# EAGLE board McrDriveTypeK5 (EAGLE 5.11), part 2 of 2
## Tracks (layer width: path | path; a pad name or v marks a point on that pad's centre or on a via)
BUZZ  (via drill 0.4)
  Top 0.254: U$25.B 15.87,66.99 21.91,67 v28.1,73.19
  Bottom 0.254: v28.1,73.19 33.18,73.19 U1.CN5-25
ENC_A  (via drill 0.4)
  Top 0.254: v27.46,53.82 23.65,53.82 21.91,53.82 v21.27,54.45
  Bottom 0.254: v27.46,53.82 29.21,53.82 30.8,55.41 32.54,55.41 33.81,54.13 U1.CN5-9 | IC1.10 17.3,55.56 17.78,56.04 20.64,56.04 21.27,55.41 v21.27,54.45 | U1.CN5-9
ENC_AA
  Bottom 0.254: IC1.11 16.03,49.16 3.97,37.15 3.97,33.97 5.4,32.54 5.4,22.17 R9.1 6.51,20.8 8.57,18.73 8.57,18.1 10.32,16.35 CN20.P$3 10.32,9.05 CN14.4
ENC_B  (via drill 0.4)
  Top 0.254: v26.67,52.86 24.45,52.86 20.48,52.86 v19.84,52.71
  Bottom 0.254: v26.67,52.86 32.7,52.86 33.97,51.59 U1.CN5-7 | v19.84,52.71 IC1.8
FL_FREE  (via drill 0.4)
  Top 0.254: U$13.P$21 26.2,33.66 28.26,35.72 v28.73,35.72 28.73,39.85 30.64,41.75 30.64,63.02 U1.CN5-18
  Bottom 0.254: R96.1 | v28.73,35.72 R96.1
FL_PWM  (via drill 0.4)
  Top 0.254: U$13.P$23 24.9,35.7 v24.92,35.72 28.1,38.89 v28.1,40.64 | v36.51,40.64 38.42,42.55 v38.42,61.75
  Bottom 0.254: R93.2 | v24.92,35.72 R93.2 | v38.42,61.75 | v38.42,61.75 U1.CN5-15 | v28.1,40.64 v36.51,40.64
FL_PWML  (via drill 0.4)
  Top 0.254: v26.83,35.72 25.55,34.44 U$13.P$22 | v26.83,35.72
  Bottom 0.254: R94.2 | v26.83,35.72 R94.2
FL_REV  (via drill 0.4)
  Top 0.254: U$13.P$19 27.5,34.17 28.1,34.77 29.69,34.77 v30.64,35.72 30.64,40.8 33.18,43.34 33.18,45.24 U1.CN5-3
  Bottom 0.254: v30.64,35.72 R95.2
FR_FREE  (via drill 0.4)
  Top 0.254: U$31.P$21 74.46,33.66 76.52,35.72 v76.99,35.72 76.99,48.1 79.22,50.32 81.44,50.32 U1.CN6-20 | U1.CN6-20
  Bottom 0.254: v76.99,35.72 R73.1 | R73.1
FR_PWM  (via drill 0.4)
  Top 0.254: U$31.P$23 73.16,35.7 v73.18,35.72 73.18,36.04 v73.18,40.64 | v41.27,40.64 v41.27,59.21
  Bottom 0.254: R70.2 | v73.18,35.72 R70.2 | v41.27,59.21 U1.CN5-13 | v41.27,40.64 v73.18,40.64
FR_PWML  (via drill 0.4)
  Top 0.254: U$31.P$22 73.81,34.44 v75.09,35.72
  Bottom 0.254: v75.09,35.72 R71.2 | R71.2
FR_REV  (via drill 0.4)
  Top 0.254: U$31.P$19 75.76,34.01 76.52,34.77 77.95,34.77 v78.9,35.72 78.9,47.78 U1.CN6-21
  Bottom 0.254: v78.9,35.72 R72.2 | R72.2 | U1.CN6-21
GND  (via drill 0.4)  (4 unrouted)
  Top 0.254: v21.59,27.46 22.22,28.26 22.3,28.18 | 28.57,28.26 U$13.P$29 | U$13.P$2 22.3,24.05 20.8,22.54 v20.8,21.59 | 31.75,28.26 31.75,27.46 | 31.75,27.46 31.75,27.41 | U$5.P$2 34.37,24.05 33.81,23.5 33.5,23.18 32.86,22.54 v32.86,21.59 | 33.65,28.26 v33.65,27.46 | 45.72,28.26 v45.72,27.46 | U$11.P$2 46.43,24.05 45.88,23.5 45.56,23.18 44.93,22.54 v44.93,21.59 | v14.45,28.26 14.45,28.1 | U$19.P$2 58.5,24.05 57.94,23.5 57.63,23.18 56.99,22.54 v56.99,21.59 | U$31.P$2 70.56,24.05 70.01,23.5 69.69,23.18 69.06,22.54 v69.06,21.59 | 57.78,28.26 v57.78,27.46 C43.1 | 69.85,28.26 v69.85,27.46 C19.1 | 31.75,27.46 C13.1 | 43.97,28.26 C41.1
  Top 0.305: U$13.P$18 28.49,31.83 U$13.P$17 | U$5.P$18 40.52,31.83 U$5.P$17 | U$11.P$17 52.62,31.83 U$11.P$18 | U$31.P$17 76.74,31.83 U$31.P$18 | U$19.P$17 64.67,31.83 U$19.P$18
  Top 0.61: U$7.P$6 14.98,27.57 14.45,28.1 14.45,30.72 | U$7.P$11 15.59,20.52 v15.4,20.48 13.65,22.23 13.65,27.46 v14.45,28.26 | 14.45,30.72 13.69,30.72 U$7.P$14 | 14.45,30.72 U$7.P$9
  Top 1.016: 28.49,31.83 28.49,28.35 28.57,28.26 | 40.52,31.83 40.52,28.26 40.64,28.26 | 52.62,31.83 52.62,28.26 52.7,28.26 | 64.67,28.26 64.67,31.83 | 76.74,31.83 76.74,28.26 76.83,28.26 | 11.66,18.17 13.97,20.48 v15.4,20.48 | 20.83,28.83 v19.53,30.16 v19.53,28.89 20.83,28.83 | 20.83,28.83 21.27,28.26
  Top 1.27: 80.17,28.26 80.17,27.25
  Top 3: v82.07,28.26 80.17,28.26 76.83,28.26 69.85,28.26 64.67,28.26 57.78,28.26 52.7,28.26 45.72,28.26 43.97,28.26 40.64,28.26 33.65,28.26 31.75,28.26 28.57,28.26 22.22,28.26 21.27,28.26
  Bottom 0.254: C29.1 R90.1 v21.59,27.46 | C40.1 R6.1 v33.65,27.46 | C50.1 R24.1 v45.72,27.46 | v15.4,20.48 14.13,19.21 13.18,19.21 R56.1 | R54.1 12.91,29.79 14.34,28.37 v14.45,28.26 | 49.05,37.94 R27.1 | 49.05,37.94 54.77,37.94 | 54.77,37.94 R29.1 | 54.77,37.94 61.12,37.94 | 61.12,37.94 66.83,37.94 | 66.83,37.94 73.18,37.94 | 73.18,37.94 78.9,37.94 | 78.9,37.94 R72.1 | 73.18,37.94 R70.1 | 66.83,37.94 R48.1 | 61.12,37.94 R39.1 | 24.92,37.94 30.64,37.94 | 30.64,37.94 36.99,37.94 | 36.99,37.94 42.7,37.94 | 42.7,37.94 49.05,37.94 | 24.92,37.94 R93.1 | 30.64,37.94 R95.1 | 36.99,37.94 R15.1 | 42.7,37.94 R17.1 | 84.45,37.15 82.39,37.94 78.9,37.94 | v57.78,27.46 R36.1 C55.1 | C60.1 R66.1 v69.85,27.46 | R55.1 12.75,25.35 v13.65,24.45 | 22.07,37.94 24.92,37.94 | C21.1
  Bottom 0.305: U$33.P$1 69.06,13.81 | U$21.P$1 56.99,14.13 | U$18.P$1 44.93,13.81 | 32.86,13.81 U$10.P$1 | U$4.P$1 20.8,13.81 | R70.1 | R15.1
  Bottom 0.406: 79.37,45.24 83.5,45.24 | 79.37,47.78 83.5,47.78 | 79.37,50.32 83.5,50.32 | 79.37,52.86 83.5,52.86 | 79.37,55.41 84.14,55.41 | 79.37,57.95 83.5,57.95 | 82.71,45.24 U1.CN6-26 81.44,45.24 81.44,43.02 | 3.02,48.26 3.33,48.58 | 3.02,48.26 | C58.2 77.47,23.13 77.47,20.48 | C53.2 65.4,23.13 65.4,20.48 | C48.2 53.34,23.13 53.34,20.48 | C31.2 41.27,23.13 41.27,20.48 | C25.2 29.21,23.13 29.21,20.48 | 79.37,60.48 83.5,60.48 | 79.37,63.02 83.5,63.02 | 79.06,73.19 83.82,73.19 | 79.06,70.65 83.82,70.65 | 79.06,68.11 83.82,68.11 | 79.06,65.56 83.82,65.56
  Bottom 0.61: 20.8,13.81 20.8,15.72 | 32.86,13.81 32.86,15.72 | 44.93,13.81 44.93,15.72 | 56.99,13.81 56.99,14.13 56.99,15.72 | 69.06,13.81 69.06,15.72
  Bottom 0.813: C35.1 70.17,63.08 70.17,70.49 | 70.17,70.49 | 70.17,70.49 IC9.5 | 70.17,70.49 IC9.4 | 3.02,48.26 3.33,48.58 4.92,48.58
  Bottom 1.016: C21.1 v19.53,30.16 | 77.63,13.97 77.63,19.37 | 65.56,13.97 65.56,19.37 | 53.5,13.97 53.5,19.37 | 41.43,13.97 41.43,19.37 | 29.37,13.97 29.37,19.37
  Bottom 3: 21.11,20.48 29.21,20.48 41.27,20.48 53.34,20.48 65.4,20.48 77.47,20.48 79.06,20.48 arc90 82.07,23.5 v82.07,27.15 v82.07,29.37 82.07,33.02 85.72,36.67 92.07,36.67 CN11.2
  other vias: 1.43,24.92 12.06,34.13 82.23,39.37 98.74,29.53 92.23,23.97 89.38,27.46 97,71.44 99.06,70.96 94.14,50.96 92.07,50.96 97.95,73.66 92.07,48.9 29.37,42.39 20.64,35.72 18.57,40.48 83.82,40.96 80.64,40.96 80.8,36.99 82.55,36.99 80.64,32.7 83.34,33.02 81.6,35.72 96.2,53.02 98.27,48.9 96.2,48.9 92.07,53.02 86.36,48.1 94.14,53.02 26.67,43.34 23.65,42.7 20.64,38.26 1.43,28.42 71.91,76.36 44.29,93.98 23.97,73.5 25.56,89.38 37.15,85.73 89.69,39.53 98.27,23.81 89.22,17.3 98.27,11.75 98.27,17.62 89.69,23.18 13.49,35.88 26.03,90.96 20.48,83.5 3.33,60.64 3.17,69.37 6.98,72.87 11.59,69.85 14.92,69.85 26.19,86.04 13.02,79.06 36.83,83.34 9.52,82.23 13.18,63.34 86.2,51.12 1.59,44.13 1.59,46.2 8.73,13.97 16.99,42.7 14.29,40.16 12.22,37.94 1.11,15.4 8.73,10.95 1.9,73.98 18.26,90.96 21.91,43.97 89.06,50.96 98.9,46.67 87.47,6.19 90.65,3.33 12.86,3.81 98.27,50.96 96.2,50.96 98.27,53.02 94.14,48.9 97,76.2 74.61,76.52 81.76,90.33 78.58,87.63 83.5,89.22 74.61,78.9 81.91,79.53 84.61,79.69 89.85,78.58 86.36,77.79 87.79,76.68 33.02,76.84 35.08,78.42 36.83,79.06 26.03,84.46 30.32,79.06 26.99,77.15 26.99,79.06 38.73,75.41 39.53,84.77 49.37,93.98 54.61,87.31 54.13,93.98 52.55,78.9 58.9,93.98 29.21,77.79 34.61,76.84 15.56,63.82 10.64,63.66 9.21,62.39 8.41,60.48 8.57,58.74 3.02,62.71 3.17,64.45 1.43,63.82 1.59,61.28 1.43,59.21 3.02,71.91 9.05,70.64 7.14,74.61 3.97,76.36 6.19,78.74 11.59,78.58 14.6,78.42 10.95,60.64 98.74,60.48 96.52,58.9 97.95,58.1 94.93,57.47 96.2,56.04 94.77,54.93 92.71,5.08 10.79,74.3 14.29,74.3 12.54,73.18 10.79,72.07 14.29,72.07 87.15,85.73 86.52,84.46 79.69,86.04 71.91,78.9 88.9,83.66 85.25,86.36 81.44,87 85.25,87.79 80.33,89.06 82.39,77.47 84.61,76.36 93.03,62.71 87.79,62.39 86.04,60.8 90.96,61.44 90.96,57.63 90.33,59.85 84.77,57.94 84.77,55.4 84.77,52.86 11.43,80.33 9.52,80.8 10.32,79.53 14.13,80.17 24.76,75.25 23.97,78.11 41.43,75.57 43.97,68.42 41.12,64.14 40.32,69.69 45.24,75.25 42.7,60.48 45.56,51.28 45.24,60.01 43.97,44.13 45.72,42.55 44.93,46.67 66.2,45.4 68.26,47.63 70.17,47.63 68.1,45.56 53.82,44.45 65.88,43.18 56.99,78.9 60.17,84.3 54.61,83.98 21.11,62.71 21.43,64.14 23.65,63.66 23.02,61.6 13.65,57.79
  pour Top (isolate 0.406, rank 2): -0.16,75.09 -0.16,32.54 100.17,32.54 100.17,75.09 80,95 20,95
  pour Bottom (isolate 0.406, rank 2): -0.16,75.09 -0.16,32.54 100.17,32.54 100.17,75.09 80,95 20,95
  pour Bottom (isolate 0.406): 100.17,-0.16 100.17,33.02 79.53,33.02 79.53,-0.16
  pour Bottom (isolate 0.254): -0.16,32.7 18.26,32.7 18.26,20.48 16.67,18.73 13.33,14.61 13.33,-0.16 -0.16,-0.16
  pour Top (isolate 0.254): -0.16,32.7 18.26,32.7 18.26,20 18.26,8.26 13.65,4.13 13.65,0 -0.16,-0.16
  pour Top (isolate 0.406): 100.17,33.34 79.22,33.34 79.22,-0.16 100.17,-0.16
  pour Bottom (isolate 0.406): 14.29,14.45 20.32,21.91 80.17,21.91 80.01,-0.16 14.29,-0.16 14.29,5.72 14.29,8.41
  pour Bottom (isolate 0.61): 59.21,49.37 72.87,49.37 76.68,45.56 78.58,43.5 78.58,81.44 59.21,81.44
  pour Top (isolate 0.61): 59.21,49.37 78.58,49.37 78.58,79.85 59.21,79.85
  pour Bottom (isolate 0.406, no thermals): 99.38,47.15 99.38,54.45 96.84,54.45 96.68,48.26 97.79,47.15
  pour Bottom (isolate 0.406, no thermals): 89.69,34.77 97.16,34.77 97.16,38.89 89.69,38.89
  pour Top (isolate 0.406, no thermals): 89.85,34.77 97.63,34.77 97.63,38.89 89.85,38.89
GYRO  (via drill 0.4)
  Top 0.254: v69,61.28 74.29,61.28 77.47,64.45 CN13.P$1
  Bottom 0.254: C34.2 | R63.2 v69,61.28
  Bottom 0.406: R63.2 C34.2 67.42,64.76 IC9.1
GYRO2
  Top 0.254: CN15.2 80.17,77.31 77.47,74.61 CN13.P$3
LED  (via drill 0.4)
  Top 0.254: v23.02,57.15 26.83,60.96 v26.83,66.84
  Top 0.61: LED3.K 2.54,34.93 v5.71,34.93
  Bottom 0.254: v5.71,34.93 5.71,37.31 23.02,54.61 v23.02,57.15 | v26.83,66.84 27.46,66.84 U1.CN5-20
LED_B  (via drill 0.4)
  Top 0.254: v43.34,88.43 43.34,85.89 U1.CN4-3
  Bottom 0.254: U$36.B 43.35,90.5 v43.34,88.43
LED_G
  Bottom 0.254: U$37.B 23.49,86.36 24.45,87.31 37.15,87.31 38.58,85.89 45.88,85.89 U1.CN4-6 | U1.CN4-6
LED_R  (via drill 0.4)
  Top 0.254: v40.48,89.22 40.48,88.74 U1.CN4-2
  Bottom 0.254: U$35.B 40.48,90.79 v40.48,89.22
N$1  (via drill 0.4, 0.6)
  Top 0.254: U$5.P$11 40.22,23.92 41.27,22.86 41.27,22.17 C2.2 41.43,21.8 41.43,16.04 40.48,15.08 38.58,15.08
  Top 1.016: v38.58,18.1 38.58,15.08 38.58,13.81 39.21,9.37 CN4.P$2
  Bottom 0.813: U$9.P$6 41.43,9.37 42.7,9.37 42.7,7.94 42.07,7.94 41.43,7.94 U$9.P$6 | U$9.P$6 | U$9.P$6 U$9.P$5
  Bottom 1.016: U$9.P$1 38.89,18.1 v38.58,18.1 | v38.58,18.1 37.78,18.1 v38.58,16.99 39.85,18.1 v38.58,18.1
  Bottom 1.778: CN4.P$2 40,5.88 arc90 42.07,7.94
N$2  (via drill 0.4)
  Top 0.254: U$13.P$24 24.25,34.49 23.49,35.24 v23.02,35.72
  Bottom 0.254: v23.02,35.72 23.02,36.04 R1.1
N$3
  Top 0.254: U$13.P$15 30.1,33.33 C26.1
N$4
  Bottom 0.254: R80.1 66.67,90.12 CN7.P$2
N$6  (via drill 0.4)
  Top 0.254: U$13.P$20 26.85,30.5 26.67,30.32 21.91,30.32 21.65,30.58 U$13.P$28 21.61,31.51 21.59,31.53 | 21.59,31.53 20.89,31.53 v20.64,31.28 | 21.59,31.53 21.65,31.53
  Bottom 0.254: R91.2 R92.2 C29.2 24.08,26.2 21.27,26.2 20.64,26.83 v20.64,31.28
N$7
  Top 0.254: CN13.P$2 81.44,70.65 U1.CN6-6
N$8  (via drill 0.4, 0.6)
  Top 0.254: U$5.P$4 35.67,23.76 34.92,23.02 34.92,22.23 C11.2 34.82,20.9 35.72,20 v35.72,18.1
  Top 1.016: v35.72,18.1 v35.72,16.99 35.72,15.4 35.72,13.81 36.67,9.37 CN4.P$1
  Bottom 0.813: U$10.P$8 33.18,9.37 34.45,9.37 34.45,7.94 33.81,7.94 33.18,7.94 U$10.P$8 | U$10.P$8 | U$10.P$8 U$10.P$7
  Bottom 1.016: v35.72,18.1 U$10.P$3 | v35.72,18.1 35.4,18.1 | v35.72,18.1 34.13,18.1 v35.72,16.99 36.19,18.1 v35.72,18.1
  Bottom 1.778: CN4.P$1 35.88,5.88 arc-90 33.81,7.94
N$9  (via drill 0.6)
  Top 0.254: U$5.P$10 39.57,23.78 40.48,22.86 40.48,16.67 v40.16,16.35
  Bottom 0.813: U$9.P$2 v40.16,16.35
N$11  (via drill 0.4)
  Top 0.254: U$13.P$25 23.6,33.07 v23.34,33.34
  Bottom 0.254: v23.34,33.34 23.34,32.23 24.76,30.8 28.05,30.8 R91.1
N$14  (via drill 0.4)
  Top 0.254: U$7.P$7 16.1,28.67 v15.56,29.21
  Bottom 0.254: v15.56,29.21 15.56,30.91 R57.1 R13.2
N$15
  Bottom 0.254: R13.1 17.62,33.23 TR1.B
N$16  (via drill 0.6)
  Top 0.254: U$5.P$12 40.87,24.06 41.75,23.18 42.07,22.86 42.7,22.23 v42.7,16.35
  Bottom 0.254: 42.7,16.51 v42.7,16.35
  Bottom 0.813: U$9.P$4 42.7,16.51
N$17  (via drill 0.6)
  Top 0.254: U$5.P$5 36.32,23.62 35.72,23.02 35.72,21.12 36.99,19.85 v36.99,16.35
  Bottom 0.813: U$10.P$4 v36.99,16.35
N$18  (via drill 0.6)
  Top 0.254: U$5.P$3 35.02,23.91 34.13,23.02 33.81,22.7 33.81,16.99 v34.45,16.35
  Bottom 0.813: v34.45,16.35 34.45,15.88 U$10.P$2
N$19
  Top 0.254: U$5.P$9 38.92,23.63 39.53,23.02 39.53,22.12 C2.1
N$20
  Top 0.61: LED3.A R14.1
N$21  (via drill 0.4, 0.6)
  Top 0.254: 26.51,15.08 28.42,15.08 29.37,16.04 29.37,21.43 29.47,21.54 C22.2 29.32,22.76 28.15,23.92 U$13.P$11
  Top 1.016: v26.51,18.1 26.51,15.08 26.51,13.81 27.15,9.37 CN1.P$2
  Bottom 1.016: v26.51,16.99 v26.51,18.1 25.72,18.1 v26.51,16.99 | v26.51,16.99 26.83,18.1 U$3.P$1 | v26.51,16.99 27.78,18.1 v26.51,18.1 | CN1.P$2 29.37,6.19 U$3.P$6 29.37,9.05 30.64,9.05
  Bottom 1.676: U$3.P$5 arc-90 27.94,5.88 CN1.P$2
N$22
  Top 0.254: C11.1 36.62,23.13 36.99,23.5 36.99,24.99 U$5.P$6
N$23  (via drill 0.4)
  Top 0.254: v32.54,32.86 32.7,32.7 33.97,32.7 34.37,32.31 U$5.P$27
  Bottom 0.254: R6.2 33.81,30.43 33.81,31.59 v32.54,32.86
N$24  (via drill 0.4)
  Top 0.254: U$5.P$7 U$5.P$8 37.94,25.56
  Top 0.61: 37.94,25.56 v37.94,23.34
  Bottom 0.254: v37.94,23.34 C31.1
N$25
  Top 0.254: U$5.P$16 41.52,33.15 C38.2
N$26
  Top 0.254: C22.1 27.52,22.97 26.85,23.63 U$13.P$9
N$27  (via drill 0.4, 0.6)
  Top 0.254: v23.65,18.1 23.65,20 22.75,20.9 C23.2 22.75,22.91 23.6,23.76 U$13.P$4
  Top 1.016: v23.65,18.1 v23.65,16.99 23.65,13.81 24.61,9.37 CN1.P$1
  Bottom 1.016: v23.65,16.99 v23.65,18.1 22.38,18.1 v23.65,16.99 | v23.65,16.99 v23.65,18.1 | v23.65,16.99 v23.65,18.1 | v23.65,16.99 U$4.P$3 | v23.65,16.99 24.13,18.1 v23.65,18.1 | CN1.P$1 22.38,6.19 U$4.P$7 22.38,9.05 21.11,9.05
  Bottom 1.676: U$4.P$8 arc90 23.65,5.88 CN1.P$1
N$28  (via drill 0.4)
  Top 0.254: v33.97,33.66 33.97,33.5 35.02,32.45 U$5.P$26
  Bottom 0.254: v33.97,33.66 33.97,32.86 36.51,30.32 38.36,30.32 R8.1
N$29  (via drill 0.4)
  Top 0.254: v35.08,35.72 36.32,34.49 U$5.P$24
  Bottom 0.254: R19.1 35.08,36.04 v35.08,35.72
N$30
  Bottom 0.61: IC9.7 IC9.6
N$31
  Top 0.254: U$5.P$15 42.17,33.33 C38.1
N$32  (via drill 0.4)
  Top 0.254: v32.7,31.28 32.94,31.51 U$5.P$28 33.72,30.58 33.97,30.32 38.73,30.32 38.92,30.5 U$5.P$20
  Bottom 0.254: R8.2 R7.2 | R8.2 | R8.2 C40.2 36.14,26.2 33.5,26.2 32.7,26.99 v32.7,31.28
N$33  (via drill 0.4)
  Top 0.254: v35.4,33.34 35.67,33.07 U$5.P$25
  Bottom 0.254: v35.4,33.34 35.4,32.23 36.83,30.8 40.11,30.8 R7.1
N$37
  Top 0.254: C23.1 24.55,23.13 24.92,23.5 24.92,24.99 U$13.P$6
N$39  (via drill 0.4, 0.6)
  Top 0.254: 50.64,15.08 52.55,15.08 53.5,16.04 53.5,21.86 C42.2 53.34,22.02 53.34,22.86 52.28,23.92 U$11.P$11
  Top 1.016: v50.64,18.1 50.64,15.08 50.64,13.81 51.28,9.37 CN3.P$2
  Bottom 1.016: v50.64,18.1 v50.64,16.99 | v50.64,16.99 50.96,18.1 U$12.P$1 | v50.64,18.1 49.85,18.1 v50.64,16.99 | v50.64,16.99 51.91,18.1 v50.64,18.1 | CN3.P$2 53.5,6.19 U$12.P$6 53.5,9.05 54.77,9.05
  Bottom 1.676: U$12.P$5 arc-90 52.23,5.88 CN3.P$2
N$40  (via drill 0.4, 0.6)
  Top 0.254: U$11.P$4 47.73,23.76 46.99,23.02 46.99,22.33 C44.2 46.88,20.9 47.78,20 v47.78,18.1
  Top 1.016: v47.78,18.1 v47.78,16.99 47.78,13.81 48.74,9.37 CN3.P$1
  Bottom 1.016: v47.78,16.99 v47.78,18.1 | v47.78,18.1 U$18.P$3 | v47.78,18.1 46.2,18.1 v47.78,16.99 | v47.78,16.99 48.26,18.1 v47.78,18.1 | CN3.P$1 46.51,6.19 U$18.P$7 46.51,9.05 45.24,9.05
  Bottom 1.676: U$18.P$8 arc90 47.62,5.88 CN3.P$1
N$41  (via drill 0.6)
  Top 0.254: U$11.P$10 51.63,23.78 52.55,22.86 52.55,16.67 v52.23,16.35
  Bottom 0.813: U$12.P$2 v52.23,16.35
N$42  (via drill 0.6)
  Top 0.254: U$11.P$12 52.93,24.06 54.77,22.23 v54.77,16.35
  Bottom 0.813: U$12.P$4 v54.77,16.35
N$43  (via drill 0.6)
  Top 0.254: U$11.P$5 48.38,23.62 47.78,23.02 47.78,21.12 49.05,19.85 v49.05,16.35
  Bottom 0.813: U$18.P$4 v49.05,16.35
N$44  (via drill 0.6)
  Top 0.254: U$11.P$3 47.08,23.91 46.2,23.02 45.88,22.7 45.88,16.99 v46.51,16.35
  Bottom 0.813: U$18.P$2 v46.51,16.35
N$46
  Bottom 0.254: CN20.P$4 12.22,16.19 10.64,17.78 9.68,17.78 9.05,18.42 9.05,19.37 7.62,20.8 7.62,22.7 R10.1 6.19,24.13 6.19,32.7 4.6,34.29 4.6,36.99 18.57,50.9 IC1.9
N$47
  Top 0.254: C42.1 51.59,21.96 51.59,23.02 50.98,23.63 U$11.P$9
N$48
  Top 0.254: U$11.P$6 49.03,23.32 48.74,23.02 48.74,22.28 C44.1
N$49  (via drill 0.4)
  Top 0.254: v44.61,32.86 44.77,32.7 46.04,32.7 46.43,32.31 U$11.P$27
  Bottom 0.254: R24.2 45.88,30.43 45.88,31.59 45.56,31.91 v44.61,32.86
N$50  (via drill 0.4)
  Top 0.254: U$11.P$8 U$11.P$7 50.01,25.56
  Top 0.61: 50.01,25.56 v50.01,23.34
  Bottom 0.254: v50.01,23.34 C48.1 | v50.01,23.34
N$51
  Top 0.254: U$11.P$16 53.58,33.15 C49.2
N$52  (via drill 0.4)
  Top 0.254: v46.04,33.66 46.04,33.5 47.08,32.45 U$11.P$26
  Bottom 0.254: v46.04,33.66 46.04,32.86 48.58,30.32 50.43,30.32 R26.1
N$53  (via drill 0.4)
  Top 0.254: U$11.P$24 48.38,34.49 v47.15,35.72
  Bottom 0.254: v47.15,35.72 47.15,36.2 R31.1
N$54
  Top 0.254: U$11.P$15 54.23,33.33 C49.1
N$55  (via drill 0.4)
  Top 0.254: U$11.P$20 50.98,30.5 50.8,30.32 46.04,30.32 45.78,30.58 U$11.P$28 45,31.51 v44.77,31.28
  Bottom 0.254: R25.2 R26.2 C50.2 48.21,26.2 45.56,26.2 44.77,26.99 v44.77,31.28
N$56  (via drill 0.4)
  Top 0.254: v47.47,33.34 47.73,33.07 U$11.P$25
  Bottom 0.254: v47.47,33.34 47.47,32.23 48.89,30.8 52.18,30.8 R25.1
N$57  (via drill 0.6)
  Top 0.254: U$13.P$10 27.5,23.78 28.42,22.86 28.42,16.67 v28.1,16.35
  Bottom 0.813: U$3.P$2 v28.1,16.35
N$58  (via drill 0.6)
  Top 0.254: U$13.P$12 28.8,24.06 29.69,23.18 29.84,23.02 30.64,22.23 v30.64,16.35
  Bottom 0.813: v30.64,16.35 30.64,15.88 U$3.P$4
N$61  (via drill 0.6)
  Top 0.254: U$13.P$5 24.25,23.62 23.65,23.02 23.65,21.12 24.92,19.85 | 24.92,19.85 | v24.92,16.35 24.92,19.85
  Bottom 0.813: v24.92,16.35 24.92,15.72 U$4.P$4
N$62
  Top 0.61: U$25.C 8.41,67.63 BZ1.-
N$65  (via drill 0.6)
  Top 0.254: U$13.P$3 22.95,23.91 22.07,23.02 | 22.07,23.02 21.75,22.7 21.75,20.8 21.75,16.99 v22.38,16.35 | 22.07,23.02
  Bottom 0.813: v22.38,16.35 22.38,15.88 U$4.P$2
N$66  (via drill 0.4)
  Top 0.254: v20.48,32.86 20.64,32.7 21.91,32.7 22.3,32.31 U$13.P$27
  Bottom 0.254: R90.2 21.75,30.48 21.75,31.59 v20.48,32.86
N$67  (via drill 0.4)
  Top 0.254: v21.91,33.66 21.91,33.5 22.95,32.48 U$13.P$26
  Bottom 0.254: v21.91,33.66 21.91,32.86 24.45,30.32 26.3,30.32 R92.1
N$68
  Bottom 0.254: R44.1 21.75,84.46 24.29,84.46 U$37.E
N$69
  Bottom 0.254: R45.1 21.43,86.36 22.86,87.79 40.64,87.79 42.21,89.36 U$36.E
N$70  (via drill 0.4, 0.6)
  Top 0.254: 62.71,15.08 64.61,15.08 65.56,16.04 65.56,21.86 C51.2 65.4,22.02 65.4,22.86 64.35,23.92 U$19.P$11
  Top 1.016: v62.71,18.1 62.71,15.08 62.71,13.81 63.34,9.37 CN5.P$2
  Bottom 0.813: U$20.P$6 65.56,9.37 66.83,9.37 U$20.P$5 | U$20.P$5 66.83,7.94 66.2,7.94 65.56,7.94 U$20.P$6 | U$20.P$5 U$20.P$6
  Bottom 1.016: v62.71,18.1 v62.71,16.99 | v62.71,16.99 63.02,18.1 U$20.P$1 | v62.71,18.1 61.91,18.1 v62.71,16.99 | v62.71,16.99 63.98,18.1 v62.71,18.1
  Bottom 1.778: CN5.P$2 64.13,5.88 arc90 66.2,7.94
N$71  (via drill 0.4, 0.6)
  Top 0.254: v59.85,18.1 59.85,20 58.95,20.9 C52.2 59.05,22.33 59.05,23.02 59.8,23.76 U$19.P$4
  Top 1.016: v59.85,18.1 v59.85,16.99 59.85,15.4 59.85,13.81 60.8,9.37 CN5.P$1
  Bottom 0.813: U$21.P$8 57.31,9.37 58.58,9.37 U$21.P$7 | U$21.P$7 58.58,7.94 57.94,7.94 57.31,7.94 U$21.P$8 | U$21.P$7 U$21.P$8
  Bottom 1.016: v59.85,18.1 59.53,18.1 | 59.53,18.1 v59.85,16.99 | v59.85,16.99 v59.85,18.1 | v59.85,16.99 U$21.P$3 | v59.85,18.1 58.26,18.1 v59.85,16.99 | v59.85,16.99 60.32,18.1 59.53,18.1
  Bottom 1.778: CN5.P$1 60.01,5.88 arc-90 57.94,7.94
N$72  (via drill 0.6)
  Top 0.254: U$19.P$10 63.7,23.78 64.61,22.86 64.61,16.67 v64.29,16.35
  Bottom 0.813: U$20.P$2 v64.29,16.35
N$73  (via drill 0.6)
  Top 0.254: U$19.P$12 65,24.06 66.83,22.23 v66.83,16.35
  Bottom 0.813: U$20.P$4 v66.83,16.35
N$74  (via drill 0.6)
  Top 0.254: U$19.P$5 60.45,23.62 59.85,23.02 59.85,21.12 61.12,19.85 v61.12,16.35
  Bottom 0.813: U$21.P$4 v61.12,16.35
N$75  (via drill 0.4)
  Top 0.254: U$13.P$7 25.88,25.56 U$13.P$8
  Top 0.61: v25.88,23.34 25.88,25.56
  Bottom 0.254: C25.1 v25.88,23.34
N$76  (via drill 0.6)
  Top 0.254: U$19.P$3 59.15,23.91 58.26,23.02 57.94,22.7 57.94,22.54 57.94,16.99 v58.58,16.35
  Bottom 0.813: U$21.P$2 v58.58,16.35
N$77
  Top 0.254: C51.1 63.66,21.96 63.66,23.02 63.05,23.63 U$19.P$9
N$78
  Top 0.254: C52.1 60.8,22.28 60.8,23.02 61.1,23.32 U$19.P$6
N$79  (via drill 0.4)
  Top 0.254: U$19.P$27 58.5,32.31 58.1,32.7 56.83,32.7 v56.67,32.86
  Bottom 0.254: v56.67,32.86 57.94,31.59 57.94,30.32 59.11,29.16 R36.2
N$80  (via drill 0.4)
  Top 0.254: U$19.P$7 62.07,25.56 U$19.P$8
  Top 0.61: 62.07,25.56 v62.07,23.34
  Bottom 0.254: v62.07,23.34 C53.1
N$81
  Top 0.254: U$13.P$16 29.45,33.15 C26.2
N$82
  Top 0.254: C54.2 65.65,33.15 U$19.P$16
N$83  (via drill 0.4)
  Top 0.254: v58.1,33.66 58.1,33.5 59.15,32.45 U$19.P$26
  Bottom 0.254: v58.1,33.66 58.1,32.86 60.64,30.32 62.49,30.32 R38.1
N$84  (via drill 0.4)
  Top 0.254: U$19.P$24 60.45,34.49 v59.21,35.72
  Bottom 0.254: v59.21,35.72 59.21,36.04 R50.1
N$85
  Top 0.254: C54.1 66.3,33.33 U$19.P$15
N$86  (via drill 0.4)
  Top 0.254: U$19.P$20 63.05,30.5 62.86,30.32 58.1,30.32 57.85,30.58 U$19.P$28 57.07,31.51 v56.83,31.28
  Bottom 0.254: R38.2 R37.2 | R38.2 | R38.2 C55.2 60.27,26.2 57.63,26.2 56.83,26.99 v56.83,31.28
N$87
  Bottom 0.254: R46.1 36.66,88.27 U$35.E
N$88  (via drill 0.4)
  Top 0.254: U$19.P$25 59.8,33.07 v59.53,33.34
  Bottom 0.254: v59.53,33.34 59.53,32.23 60.96,30.8 64.24,30.8 R37.1
N$93  (via drill 0.4, 0.6)
  Top 0.254: 74.77,15.08 76.68,15.08 77.63,16.04 77.63,21.86 C56.2 77.47,22.02 77.47,22.86 76.41,23.92 U$31.P$11
  Top 1.016: v74.77,18.1 74.77,15.08 74.77,13.81 75.41,9.37 CN2.P$2
  Bottom 1.016: v74.77,18.1 v74.77,16.99 | v74.77,16.99 75.09,18.1 U$32.P$1 | v74.77,18.1 73.98,18.1 v74.77,16.99 | v74.77,16.99 76.04,18.1 v74.77,18.1 | CN2.P$2 77.63,6.19 U$32.P$6 77.63,9.05 78.9,9.05
  Bottom 1.676: U$32.P$5 arc-90 76.36,5.88 CN2.P$2
N$94
  Bottom 1.016: U$16.IN 87.95,47.89 C16.2 90.03,44.4 D1.K
N$95  (via drill 0.4)
  Top 0.254: U$7.P$5 15.6,26.47 v15.56,26.51
  Bottom 0.254: v15.56,26.51 14.76,26.51 13.33,27.94 12.28,27.94 R54.2 10.48,27.99 R53.2
N$96
  Bottom 0.61: R40.2 1.75,9.21 CN14.1
N$97
  Bottom 1.016: U$14.P$6 U$14.P$3 90.75,40.88 D1.A
N$99
  Bottom 0.254: CN12.1 12.23,83.98 15.72,83.98 R44.2
N$100
  Bottom 0.254: R45.2 16.83,85.73 13.81,85.73 CN12.2
N$101
  Bottom 0.254: CN12.4 17.78,88.27 R46.2
N$102
  Top 0.305: R68.1 LED5.A
N$103  (via drill 0.4, 0.6)
  Top 0.254: v71.91,18.1 71.91,20 71.01,20.9 C57.2 71.12,22.17 71.12,23.02 71.86,23.76 U$31.P$4
  Top 1.016: v71.91,18.1 v71.91,16.99 71.91,13.81 72.87,9.37 CN2.P$1
  Bottom 1.016: v71.91,16.99 v71.91,18.1 | v71.91,18.1 U$33.P$3 | v71.91,18.1 70.33,18.1 v71.91,16.99 | v71.91,16.99 72.39,18.1 v71.91,18.1 | CN2.P$1 70.64,6.19 U$33.P$7 70.64,9.05 69.37,9.05
  Bottom 1.676: U$33.P$8 arc90 71.91,5.88 CN2.P$1
N$104  (via drill 0.6)
  Top 0.254: U$31.P$10 75.76,23.78 76.68,22.86 76.68,16.67 v76.36,16.35
  Bottom 0.813: U$32.P$2 v76.36,16.35
N$105  (via drill 0.6)
  Top 0.254: U$31.P$12 77.06,24.06 78.9,22.23 v78.9,16.35
  Bottom 0.813: U$32.P$4 v78.9,16.35
N$106  (via drill 0.6)
  Top 0.254: U$31.P$5 72.51,23.62 71.91,23.02 71.91,21.12 73.18,19.85 v73.18,16.35
  Bottom 0.813: U$33.P$4 v73.18,16.35
N$107  (via drill 0.6)
  Top 0.254: U$31.P$3 71.21,23.91 70.01,22.7 70.01,16.99 v70.64,16.35
  Bottom 0.813: U$33.P$2 v70.64,16.35
N$108
  Top 0.254: C56.1 75.72,21.96 75.72,23.02 75.11,23.63 U$31.P$9
N$109
  Top 0.254: C57.1 72.87,22.28 72.87,23.02 73.16,23.32 U$31.P$6
N$110  (via drill 0.4)
  Top 0.254: v17.3,62.55 21.11,66.36 22.54,66.36 29.05,72.87 29.05,73.82 v27.94,74.93 | v31.91,82.39 31.91,83.03 | 31.91,83.03 TR2.C | 31.91,83.03 33.28,84.4 R11.1
  Bottom 0.254: IC1.5 17.3,62.71 v17.3,62.55 | v27.94,74.93 31.91,78.9 v31.91,82.39
N$111  (via drill 0.4)
  Top 0.254: U$31.P$27 70.56,32.31 70.17,32.7 68.9,32.7 v68.74,32.86
  Bottom 0.254: v68.74,32.86 70.01,31.59 70.01,30.43 R66.2
N$112  (via drill 0.4)
  Top 0.254: U$31.P$7 74.14,25.56 U$31.P$8
  Top 0.61: v74.14,23.34 74.14,25.56
  Bottom 0.254: C58.1 v74.14,23.34
N$113  (via drill 0.4)
  Top 0.254: U$7.P$2 16.02,23.17 v15.4,22.54
  Bottom 0.254: v15.4,22.54 13.81,20.96 13.18,20.96 R56.2 R51.2 | R51.2
N$114  (via drill 0.4)
  Top 0.254: U$7.P$3 15.69,24.27 v15.56,24.13
  Bottom 0.254: v15.56,24.13 14.92,24.13 14.29,23.5 12.33,23.5 R55.2 10.79,23.55 R52.2
N$115
  Top 0.254: C59.2 77.71,33.15 U$31.P$16
N$116  (via drill 0.4)
  Top 0.254: v70.17,33.66 70.17,33.5 71.21,32.45 U$31.P$26
  Bottom 0.254: v70.17,33.66 70.17,32.86 72.71,30.32 74.56,30.32 R69.1
N$117  (via drill 0.4)
  Top 0.254: U$31.P$24 72.51,34.49 v71.28,35.72
  Bottom 0.254: v71.28,35.72 R74.1
N$118
  Top 0.254: C59.1 78.36,33.33 U$31.P$15
N$119
  Bottom 0.406: U$45.P$4 C32.1
N$120
  Bottom 0.406: 65.03,69.22 IC9.3 | R61.2 65.03,69.22 | C32.2 64.08,70.17 65.03,69.22
N$121
  Bottom 0.406: R62.1 61.49,64.77 C33.2 | R61.1 61.49,66.99 R62.1 | U$45.P$1 R62.1
N$122  (via drill 0.4)
  Top 0.254: U$31.P$20 75.11,30.5 74.93,30.32 70.17,30.32 69.91,30.58 U$31.P$28 69.13,31.51 v68.9,31.28
  Bottom 0.254: R67.2 R69.2 C60.2 | C60.2 | C60.2 72.34,26.2 69.69,26.2 68.9,26.99 v68.9,31.28
N$123
  Bottom 0.254: 65.93,63.98 C34.1
  Bottom 0.406: R63.1 65.93,63.98 | IC9.2 65.72,67.95 64.93,67.15 64.93,65.72 | 64.93,65.72 R62.2 | C34.1 65.62,64.72 64.93,65.72
N$124  (via drill 0.4)
  Top 0.254: v71.6,33.34 71.86,33.07 U$31.P$25
  Bottom 0.254: v71.6,33.34 71.6,32.23 73.02,30.8 76.31,30.8 R67.1
N$129
  Bottom 0.813: LCD1.P$2 3.6,54.51 C6.2
N$130
  Top 0.254: TR2.B 31.75,87.17 R28.1
N$131
  Top 0.254: R77.1 R28.2 31.75,92.08 CN10.2
N$133
  Bottom 0.813: LCD1.P$3 C5.2
N$134
  Bottom 0.813: LCD1.P$4 C5.1
N$135
  Top 0.254: R78.2 R79.2 34.29,92.39 CN10.3
P0_4
  Top 0.254: CN8.5 57.78,89.22 64.93,89.22 66.2,87.95 66.2,85.89 U1.CN3-5 | U1.CN3-5
P0_5
  Top 0.254: U1.CN3-4 63.5,88.58 57.47,88.58 56.2,89.85 54.61,89.85 CN8.4 | U1.CN3-4
P0_6
  Top 0.254: CN8.3 52.07,89.85 53.66,89.85 54.29,89.22 55.88,89.22 59.21,85.89 63.66,85.89 U1.CN3-3 | U1.CN3-3
P0_7  (via drill 0.4)
  Top 0.254: v60.01,87.16 | v60.01,87.16 U1.CN3-2
  Bottom 0.254: CN8.2 49.69,89.7 57.47,89.7 v60.01,87.16
RL_FREE  (via drill 0.4)
  Top 0.254: U$5.P$21 38.27,33.66 39.85,35.24 39.85,35.72 | 39.85,35.72 v39.85,57.95 | 39.85,35.72 v40.8,35.72
  Bottom 0.254: v40.8,35.72 R18.1 | v40.8,35.72 | v39.85,57.95 33.18,57.95 U1.CN5-14
RL_PWM  (via drill 0.4)
  Top 0.254: U$5.P$23 36.97,35.7 v36.99,35.72 36.99,39.53 v38.89,41.43 | v49.69,41.43 49.69,44.29 U1.CN4-7
  Bottom 0.254: R15.2 | v36.99,35.72 R15.2 | v38.89,41.43 v49.69,41.43
RL_PWML  (via drill 0.4)
  Top 0.254: v38.89,35.72 37.62,34.44 U$5.P$22
  Bottom 0.254: R16.2 | v38.89,35.72 R16.2
RL_REV  (via drill 0.4)
  Top 0.254: U$5.P$19 39.57,34.17 40.16,34.77 41.75,34.77 v42.7,35.72 v42.7,50.32
  Bottom 0.254: v42.7,35.72 R17.2 | U1.CN5-8 | U1.CN5-8 32.38,51.59 33.65,50.32 v42.7,50.32
RR_FREE  (via drill 0.4)
  Top 0.254: U$19.P$21 62.4,33.66 64.45,35.72 v64.93,35.72 64.93,40.16 78.9,54.13 U1.CN6-17 | U1.CN6-17
  Bottom 0.254: v64.93,35.72 R49.1 | R49.1
RR_PWM  (via drill 0.4)
  Top 0.254: U$19.P$23 61.1,35.7 v61.12,35.72 v61.12,41.75 | v48.42,42.39 48.42,83.34 U1.CN4-5
  Bottom 0.254: v61.12,35.72 R39.2 | v48.42,42.39 50.48,42.39 51.12,41.75 v61.12,41.75
RR_PWML  (via drill 0.4)
  Top 0.254: U$19.P$22 61.75,34.44 v63.02,35.72
  Bottom 0.254: v63.02,35.72 R47.2 | R47.2
RR_REV  (via drill 0.4)
  Top 0.254: U$19.P$19 63.7,34.01 64.45,34.77 65.88,34.77 v66.83,35.72 66.83,40.48 79.22,52.86 81.44,52.86 U1.CN6-18 | U1.CN6-18 | U1.CN6-18
  Bottom 0.254: v66.83,35.72 R48.2
RXD2  (via drill 0.4)
  Top 0.254: v24.13,50.32 20.64,50.32 18.57,52.39 v18.57,62.55
  Bottom 0.254: U1.CN5-5 33.97,49.05 32.7,50.32 v24.13,50.32 | v18.57,62.55 IC1.6 | IC1.6
SCL  (via drill 0.4)
  Top 0.254: v20.95,47.47 20.48,47.78 v12.06,47.78
  Bottom 0.254: LCD1.P$8 7.3,45.51 R81.1 7.67,46.2 10.48,46.2 10.95,46.67 v12.06,47.78 | U1.CN5-4 22.22,46.52 v20.95,47.47
SD_CD  (via drill 0.4)
  Top 0.254: v23.97,56.36 27.78,60.17 27.78,68.11 27.62,68.9 27.62,70.33 v29.21,71.92
  Bottom 0.254: R51.1 8.25,21.12 8.25,24.29 7.14,25.4 7.14,35.56 7.14,37.94 8.57,39.37 23.97,54.77 v23.97,56.36 | v29.21,71.92 U1.CN5-24 | U1.CN5-24
SD_CLK  (via drill 0.4)
  Top 0.254: v29.05,56.83 29.69,57.47 29.69,70.01 v29.21,70.49
  Bottom 0.254: R53.1 9.52,37.31 26.83,54.61 27.62,55.41 v29.05,56.83 | v29.21,70.49 29.37,70.65 33.18,70.65 U1.CN5-23
SD_CMD  (via drill 0.4)
  Top 0.254: v25.56,56.2 28.57,59.21 v28.57,69.06
  Bottom 0.254: R52.1 8.31,25.35 7.62,26.04 7.62,37.62 9.05,39.05 25.24,55.25 v25.56,56.2 | v28.57,69.06 28.89,69.38 U1.CN5-22 | U1.CN5-22
SD_DAT0  (via drill 0.4)
  Top 0.254: v24.61,60.01 25.88,61.28 v25.88,68.11
  Bottom 0.254: v25.88,68.11 33.18,68.11 U1.CN5-21 | IC1.12 14.76,55.56 15.72,56.52 21.11,56.52 v24.61,60.01
SD_DAT0B  (via drill 0.4)
  Top 0.254: v16.67,39.21 v12.38,46.83
  Bottom 0.254: R12.1 10.79,53.02 12.7,53.02 13.49,53.82 | 13.49,53.82 IC1.13 | TR1.C v16.67,39.21 | v12.38,46.83 13.49,47.94 13.49,53.82
SDA  (via drill 0.4)
  Top 0.254: v22.54,49.05 21.75,48.74 v12.7,48.74
  Bottom 0.254: LCD1.P$7 5.15,47.1 R75.1 9.84,47.47 11.11,48.74 v12.7,48.74 | v22.54,49.05 U1.CN5-6 | U1.CN5-6
SENS_ANL
  Top 0.254: CN6.6 86.84,70.96 U1.CN6-8
SENS_ANR
  Top 0.254: U1.CN6-9 80.64,64.3 81.91,65.56 83.98,65.56 88.11,69.69 90.96,69.69 91.6,70.33 91.6,71.6 92.87,72.87 CN6.7 | U1.CN6-9 | CN6.7
SENS_CENTER
  Top 0.254: CN6.5 | CN6.5 92.87,70.33 91.6,69.06 91.6,67.63 91.12,67.15 86.84,67.15 83.98,64.3 U1.CN6-10
SENS_GATE  (via drill 0.4)
  Top 0.254: v88.58,68.42 CN6.4 | v88.58,65.09 83.98,60.48 81.44,60.48 U1.CN6-11
  Bottom 0.254: v88.58,65.09 v88.58,68.42
SENS_L1
  Top 0.254: CN6.2 86.84,65.88 83.98,63.02 79.53,63.02 78.9,63.66 78.9,64.93 79.53,65.56 80.8,65.56 81.44,66.2 81.44,68.11 U1.CN6-5
SENS_L2
  Top 0.254: CN6.3 94.14,69.69 94.14,73.98 93.34,74.77 92.39,74.77 91.6,73.98 91.6,72.87 90.96,72.23 83.03,72.23 U1.CN6-4
SENS_R1
  Top 0.254: U1.CN6-2 83.03,74.77 91.6,74.77 CN6.9
SENS_R2
  Top 0.254: U1.CN6-3 81.44,73.19 89.53,73.19 CN6.8
SV_FREE  (via drill 0.4)
  Top 0.254: U$11.P$21 50.33,33.66 52.39,35.72 v52.86,35.72
  Bottom 0.254: v52.86,35.72 R30.1 | R30.1
SV_PWM  (via drill 0.4)
  Top 0.254: v49.05,35.72 49.03,35.7 U$11.P$23 | v49.05,35.72 | v49.05,35.72 49.05,37.31 47.15,39.21 47.15,82.55 45.88,83.82 45.88,85.89 U1.CN4-4 | U1.CN4-4
  Bottom 0.254: v49.05,35.72 R27.2
SV_PWML  (via drill 0.4)
  Top 0.254: U$11.P$22 49.68,34.44 v50.96,35.72
  Bottom 0.254: v50.96,35.72 R76.1
SV_REV  (via drill 0.4)
  Top 0.254: U$11.P$19 51.63,34.01 52.39,34.77 53.82,34.77 v54.77,35.72 50.8,39.69 v50.8,52.86
  Bottom 0.254: v54.77,35.72 R29.2 | R29.2 | v50.8,52.86 41.43,52.86 37.94,52.86 33.65,52.86 32.38,54.13 U1.CN5-10
SW1
  Top 0.254: U1.CN6-25 81.44,45.24 83.5,45.24 85.25,43.5 85.25,30.64 87.31,28.58 93.03,28.58 93.34,28.26 93.34,26.67 92.55,25.88 S1.P$3
SW2
  Top 0.254: U1.CN6-24 83.18,46.52 85.72,43.97 85.72,30.96 87.63,29.05 93.34,29.05 93.82,28.58 93.82,21.12 92.55,19.85 S2.P$3 | U1.CN6-24
SW3
  Top 0.254: U1.CN6-23 81.44,47.78 83.34,47.78 86.2,44.93 86.2,31.28 87.95,29.53 93.66,29.53 94.3,28.89 94.3,15.56 92.55,13.81 S3.P$3
SW4
  Top 0.254: U1.CN6-22 83.18,49.05 86.68,45.56 86.68,31.59 88.26,30.01 93.98,30.01 94.77,29.21 94.77,10 92.55,7.78 S4.P$3 | U1.CN6-22
TXD2  (via drill 0.4)
  Top 0.254: v29.53,43.97 30.16,44.61 30.16,74.3 v29.53,74.93 | v35.08,82.55 35.08,86.36 R79.1
  Bottom 0.254: v29.53,43.97 U1.CN5-2 | v29.53,43.97 | v29.53,74.93 | v29.53,74.93 33.34,78.74 35.08,80.49 v35.08,82.55
V33  (via drill 0.4)
  Top 0.406: CN10.1 28.1,91.12 28.1,88.58 28.89,87.79 R77.2 28.1,85.78 v28.1,84.3
  Top 0.61: U$7.P$4 14.89,25.37 v14.76,25.4
  Top 0.813: 6.67,50.01 6.67,62.07 10.16,65.56 v18.7,65.56 | 6.67,50.01 6.67,45.09 5.71,44.13 LCD1.P$9 | 6.67,50.01 LCD1.P$5
  Bottom 0.254: C7.2 | 8.25,32.23 C7.2
  Bottom 0.406: U$6.OUT 25.72,71.76 26.83,72.87 26.83,75.41 28.1,76.68 v28.1,84.3
  Bottom 0.61: R57.2 17.57,25.95 16.99,25.37 14.8,25.37 v14.76,25.4 14.45,25.72 13.49,26.67 8.73,26.67 8.25,27.15 8.25,31.91 8.25,32.23 8.25,34.61 8.25,37.15 9.84,38.74 26.83,55.72 26.83,63.18 21.11,68.9 C27.1
  Bottom 0.813: C27.1 20.8,67.63 v18.7,65.56 | C6.1 C4.2 LCD1.P$5 | LCD1.P$9 5.38,44.03 R81.2 8.41,44.03 R75.2
  Bottom 1.27: C27.1 U$6.OUT
VBAT  (via drill 0.4)
  Top 0.254: U$13.P$1 21.65,24.51 21.59,24.45 21.11,23.97 19.84,22.7 v19.84,11.59 | U$5.P$1 33.72,24.35 33.65,24.29 31.91,22.54 v31.91,11.59 | U$11.P$1 45.78,24.51 45.72,24.29 43.97,22.54 v43.97,11.59 | U$19.P$1 57.85,24.35 56.04,22.54 v56.04,11.59 | U$31.P$1 69.91,24.35 68.1,22.54 v68.1,11.59 | 79.06,25.08 v79.06,25.24 | v79.85,24.29 v78.9,23.97 | 80.17,25.08 C20.2 | v79.69,23.34 | U$19.P$14 U$19.P$13 | U$11.P$14 U$11.P$13 | U$13.P$14 U$13.P$13 | 42.31,24.53 U$5.P$13 | v85.57,23.34
  Top 0.406: U$31.P$14 U$31.P$13
  Top 1.27: 85.57,24.29 v85.09,24.29 v79.85,24.29 | v85.57,25.08 v85.57,23.34 v79.69,23.34 | 78.26,25.08 79.06,25.08 80.17,25.08 v85.57,25.08 | v85.57,25.08 | v79.69,23.34 U$31.P$14 | C19.2 68.1,24.45 v67.31,23.66 | C43.2 56.04,24.45 v55.24,23.66 | C13.2 31.91,24.45 v31.11,23.66 | v31.11,23.66 30.1,24.67 U$13.P$14 30.1,25.56 31.11,25.56 | v55.24,23.66 54.23,24.67 U$11.P$14 54.23,25.56 55.24,25.56 | v67.31,23.66 66.3,24.67 U$19.P$14 66.3,25.45 C19.2 | 31.11,25.56 31.91,25.56 | v31.11,23.66 31.11,25.56 | 55.24,25.56 56.04,25.56 | v55.24,23.66 55.24,25.56 | C19.2 67.31,25.45 v67.31,23.66 | C41.2 43.97,24.45 v43.18,23.66 | v43.18,23.66 42.31,24.53 42.17,24.67 U$5.P$14 42.17,25.56 43.18,25.56 | 43.18,25.56 43.97,25.56 | v43.18,23.66 43.18,25.56
  Bottom 0.254: 19.84,25.3 C21.2 | 86.2,25.88 v85.57,25.08 | 79.69,24.93 79.69,24.45 v79.85,24.29
  Bottom 0.61: 19.84,24.93 19.84,25.3 | U$33.P$6 71.91,7.78 76.36,7.78 U$32.P$7 | U$32.P$7 76.36,9.84 71.91,9.84 U$33.P$6 | U$33.P$6 U$33.P$5 | 71.91,11.59 U$33.P$6 | U$32.P$7 76.36,11.75 | 86.2,11.59 86.25,11.59 | U$21.P$6 59.85,7.94 64.29,7.94 U$20.P$7 64.29,9.84 | 64.29,9.84 59.85,9.84 U$21.P$6 | U$21.P$6 U$21.P$5 | 59.85,11.59 U$21.P$6 | 64.29,9.84 64.29,11.59 52.23,11.59 U$12.P$7 | U$12.P$7 52.23,7.78 47.78,7.78 U$18.P$6 | U$12.P$7 52.23,9.84 47.78,9.84 U$18.P$6 | U$18.P$6 U$18.P$5 | U$18.P$6 47.78,11.59 40.16,11.59 U$9.P$7 | U$9.P$7 | U$9.P$7 40.16,7.94 35.72,7.94 U$10.P$6 | U$10.P$6 | U$9.P$7 40.16,9.84 39.69,9.84 | 36.04,9.84 35.72,9.84 | U$10.P$6 35.72,9.84 | U$10.P$6 U$10.P$5 | 35.72,9.84 35.72,11.59 28.1,11.59 U$3.P$7 | U$3.P$7 | U$3.P$7 28.1,7.78 23.65,7.78 U$4.P$6 | U$4.P$6 | U$3.P$7 28.1,9.84 23.65,9.84 | 23.65,9.84 U$4.P$6 | U$4.P$6 U$4.P$5 | 23.65,9.84 23.65,11.59 | 86.2,26.04
  Bottom 1.016: 43.5,24.93 43.18,24.77 | U$14.P$5 U$14.P$4 | U$14.P$5 U$14.P$2 | CN11.1 92.23,32.54 96.84,32.54 98.11,33.81 98.11,41.75 U$14.P$5
  Bottom 1.27: 31.11,24.93 v31.11,23.66 | 43.18,24.77 v43.18,23.66 | 55.24,24.93 v55.24,23.66 | 67.31,24.93 v67.31,23.66 | 78.58,24.93 79.69,24.93 v79.69,23.34 U$31.P$14 | U$9.P$8 39.69,9.84 36.04,9.84 | U$21.P$5 60.32,9.53 63.98,9.53
  Bottom 1.422: 21.59,11.59 v19.84,11.59 C61.1
  Bottom 1.676: 78.58,24.93 67.31,24.93 55.24,24.93 43.5,24.93 31.11,24.93 23.18,24.93 19.84,24.93
  Bottom 1.778: U$14.P$2 U$14.P$1
  Bottom 1.93: 86.25,11.59 C14.+
  Bottom 2.184: U$9.P$8 U$10.P$5 | U$21.P$5 U$20.P$8
  Bottom 2.54: U$4.P$5 U$3.P$8 | U$18.P$5 U$12.P$8 | U$33.P$5 U$32.P$8
  Bottom 3: 21.59,11.59 v31.91,11.59 v43.97,11.59 v56.04,11.59 59.85,11.59 v68.1,11.59 71.91,11.59 86.2,11.59 86.2,25.88 86.2,26.04 86.2,30.96 87.95,32.7 CN11.1
VCC  (via drill 0.4, 0.6, 1)
  Top 0.305: R68.2 98.16,62.12 v96.84,60.8
  Top 0.406: U1.CN5-1 34.45,40.8 v32.86,39.21
  Top 0.61: v3.17,42.07 R14.2 | R11.2 33.5,81.97 33.5,80.81 | 39.53,81.76 | 39.53,81.76 39.53,80.81
  Top 0.813: BZ1.+ 4.92,74.61 4.92,59.85 v3.17,58.1 v3.17,42.07 | v74.77,74.45 v74.77,64.93
  Top 1.676: U1.CN5-1 35.72,43.97 36.67,44.93 36.67,52.86 36.67,74.3 36.67,76.36 v42.07,81.76 | v42.07,81.76 v44.29,81.76 | v44.29,81.76 | v42.07,81.76 42.07,83.98 | 42.07,83.98 42.07,84.46 | 42.07,84.46 U1.CN4-1 | v44.29,81.76 42.07,83.98 | 42.07,84.46 41.91,84.46 39.53,82.08 39.53,81.76 | v43.18,82.71 43.02,82.71 v42.07,81.76 | 39.53,80.81 39.53,79.22 | 39.53,80.81 39.53,81.76 | BZ1.+ 16.67,76.68 19.37,76.68 v23.49,80.81 26.35,80.81 | 39.53,81.76 v42.07,81.76 | 26.35,80.81 arc44 26.35,80.81 | 26.35,80.81 33.5,80.81 39.53,80.81
  Bottom 0.254: R1.2 23.02,39.85 26.83,39.85 | 28.73,39.85 26.83,39.85 | 32.86,39.85 28.73,39.85 | 35.08,39.85 R19.2 | 35.08,39.85 38.89,39.85 | 38.89,39.85 40.8,39.85 | 40.8,39.85 R18.2 | 40.8,39.85 47.15,39.85 | 47.15,39.85 R31.2 | 47.15,39.85 50.96,39.85 | 50.96,39.85 52.86,39.85 | 52.86,39.85 R30.2 | 52.86,39.85 59.21,39.85 | 59.21,39.85 R50.2 | 59.21,39.85 63.02,39.85 | 63.02,39.85 64.93,39.85 | 64.93,39.85 R49.2 | 64.93,39.85 71.28,39.85 | 71.28,39.85 R74.2 | 71.28,39.85 75.09,39.85 | 75.09,39.85 76.2,39.85 R73.2 | 28.73,39.85 R96.2 | 28.73,39.85 | 32.86,39.85 35.08,39.85 | 50.96,39.85 R76.2 | R94.1 | 26.83,39.85 R94.1 | R71.1 | 75.09,39.85 R71.1 | R47.1 | 63.02,39.85 R47.1 | R16.1 | 38.89,39.85 R16.1 | v32.86,39.21 32.86,39.85 | 6.83,10.64 R40.1 | U1.CN3-1
  Bottom 0.305: 95.25,60.8 v96.84,60.8
  Bottom 0.406: 54.45,81.76 53.02,81.6 | 57.15,81.76 56.99,81.6 | 60.96,81.76 60.96,81.28 | R1.2
  Bottom 0.61: v3.17,42.07 2.86,41.43 2.86,23.97 | 2.86,23.97 2.86,22.54 R9.2 C1.2 CN20.P$1 6.32,15.43 6.83,14.92 6.83,10.64 CN14.3 | 2.86,23.97 R10.2 | 95.25,65.88 CN6.1 | U1.CN3-1 60.96,86.04 60.96,88.9 CN7.P$1 63.5,92.71 45.56,92.71 | U$35.C 43.66,92.71 U$36.C 45.56,92.71 | CN8.1 45.56,90.97 45.56,92.71 | C17.1 44.29,80.46 v44.29,81.76 | 23.49,81.6 U$37.C | v42.07,81.76
  Bottom 0.813: 10.42,56.67 8.25,56.67 6.83,58.1 v3.17,58.1 | 10.42,56.67 C3.2 arc-90 12.22,54.98 IC1.14 | 10.42,56.67 10.42,54.77 R12.2 | v74.77,64.93 C35.2 IC9.8 | C47.2 50.64,72.87 arc-90 52.23,74.45 v74.77,74.45 U1.CN6-1 | C47.2 arc-90 C47.2 | C47.2 U$45.P$3 | 77.63,81.76 CN15.1
  Bottom 1.016: 75.56,81.76 75.72,81.76
  Bottom 1.27: U$6.IN C28.2 C9.1 23.49,81.6 v23.49,80.81 | 80.17,81.76 U1.CN6-1 | U$16.OUT
  Bottom 1.676: U1.CN4-1 42.07,83.98 v44.29,81.76 | v44.29,81.76 54.45,81.76 57.15,81.76 60.96,81.76 62.39,81.76 | 62.39,81.76 U1.CN3-1 | v44.29,81.76 v42.07,81.76 U1.CN4-1 | U1.CN4-1 | U$16.OUT C46.1 92.2,55.91 C18.+ 92.71,58.1 95.25,60.64 95.25,60.8 95.25,65.88 95.25,76.52 91.09,80.68 90.01,81.76 80.17,81.76 77.63,81.76 75.56,81.76 62.39,81.76
VOL  (via drill 0.4)
  Top 0.254: v75.72,83.5 75.72,82.71 76.04,81.76 v76.04,66.84
  Bottom 0.254: v75.72,83.5 75.72,86.84 73.66,88.74 71.91,88.74 71.17,89.48 C12.2 70.06,89.85 R80.2 | v76.04,66.84 U1.CN6-7

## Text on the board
tPlace: P0_7, 6, 5, 4 | V33 | Tx | Rx | GND | VCC | GND | R | C | B | VCC | GND | G | Gyro2 | Gyro2 | Gyro | Off | On | IS-2235 | - | + | MCR driver TypeK ver.5 | DF3A-5P-2DSA | rev.048 2019.03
